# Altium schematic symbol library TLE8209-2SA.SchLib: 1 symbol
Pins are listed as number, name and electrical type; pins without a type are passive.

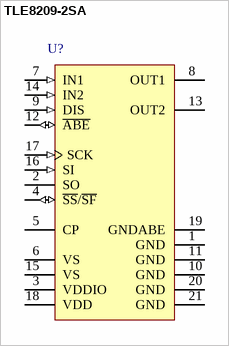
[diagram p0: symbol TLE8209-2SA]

## TLE8209-2SA
designator U?
SPI Programmable H-Bridge, 4.5 to 28 V, 125 mOhm RDS(on), PG-DSO-20-65, Reel, Green; Manufacturer: Infineon; PartNumber: TLE8209-2SA; Current Limit (min.): 7.7 A; Green: TRUE; Quiescent Current (max.): 20 uA; RthJC (max): 1.6 K/W
footprint INF-PG-DSO-20-65_N (SOP, 20-Leads, Body 15.9x11mm, Pitch 1.27mm, Thermal Pad 16.05x6mm, IPC Medium Density)
footprint INF-PG-DSO-20-65_L (SOP, 20-Leads, Body 15.9x11mm, Pitch 1.27mm, Thermal Pad 16.05x6mm, IPC High Density)
footprint INF-PG-DSO-20-65_M (SOP, 20-Leads, Body 15.9x11mm, Pitch 1.27mm, Thermal Pad 16.05x6mm, IPC Low Density)
pins: 1 GND (power) "Ground", 2 SO (hiz) "SPI Serial Data Out,no function - connect to GND", 3 VDDIO (power) "Supply Voltage for Logic Output Buffer,Switches to SF-mode if connected to GND", 4 ~{SS}/~{SF} (io) "Slave Select (low active),Status Flag (low active)", 5 CP "Pin for external Charge Pump Capacitor", 6 VS (power) "Battery Supply Voltage, has to be connected to pin 15", 7 IN1 (in) "Input 1", 8 OUT1 (power) "Output 1", 9 DIS (in) "Disable", 10 GND (power) "Ground", 11 GND (power) "Ground", 12 ~{ABE} (io) "Bidirectional Enable Pin", 13 OUT2 (power) "Output 2", 14 IN2 (in) "Input 2", 15 VS (power) "Input battery supply voltage, has to be connected to pin 6", 16 SI (in) "SPI Serial Data Input,no function - connect to GND", 17 SCK (in) "SPI Clock, no function - connect to GND", 18 VDD (power) "VDD supply", 19 GNDABE (power) "Sense ground for VDD monitoring", 20 GND (power) "Ground", 21 GND (power) "Heatslug - connect to GND"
